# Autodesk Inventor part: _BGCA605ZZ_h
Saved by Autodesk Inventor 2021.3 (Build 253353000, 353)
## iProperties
Created: 2021-10
Part Number: _BGCA605ZZ_h
Material: Generic
Document SubType Name: Modeling
Designer: Administrator
Density: 1 g/cm^3
Appearance: Default
Title: _BGCA605ZZ_h
Author: Administrator
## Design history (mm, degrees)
feature "Body1"
body "Solid1"
